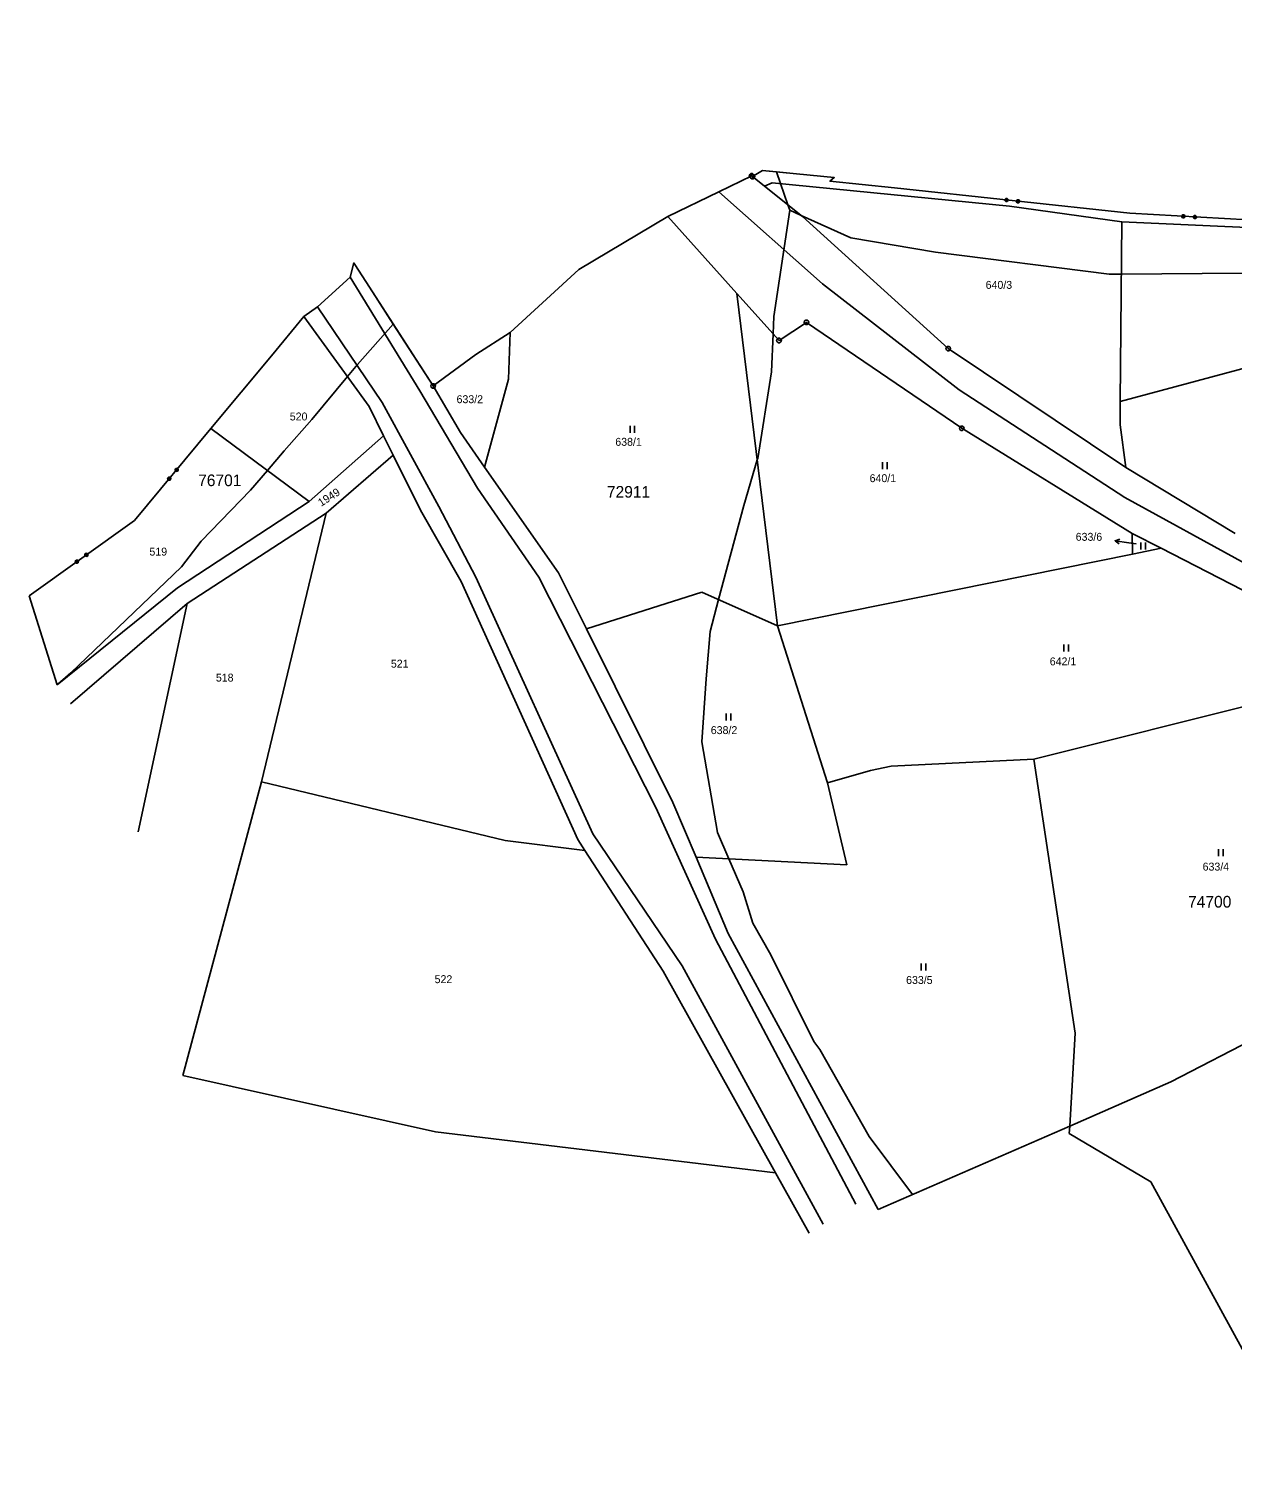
# Model space of a CAD drawing. Extents: x -789470 to -786707, y -1118640 to -1114455.
# Drawn here: x -789470 to -789211.5, y -1114767.1 to -1114454.9 of the extents above; entities that cross this region are included whole.
import ezdxf

# ---------------------------------------------------------------- set-up
doc = ezdxf.new("R2010")
doc.units = 0
for name, color, linetype in [('1', 7, 'Continuous'), ('11', 7, 'Continuous'), ('2', 7, 'Continuous'), ('3', 7, 'Continuous'), ('4', 7, 'Continuous'), ('6', 7, 'Continuous'), ('7', 7, 'Continuous'), ('8', 7, 'Continuous')]:
    doc.layers.add(name, color=color, linetype=linetype)

msp = doc.modelspace()

# ---------------------------------------------------------------- linework, layer by layer
at = {"layer": '1'}
for p, q in [((-789314.84, -1114486.39), (-789321.86, -1114489.79)), ((-789314.65, -1114486.55), (-789314.84, -1114486.39)), ((-789312.54, -1114485.23), (-789314.65, -1114486.55)), ((-789314.65, -1114486.55), (-789312.07, -1114488.61)), ((-789305.22, -1114485.95), (-789312.54, -1114485.23)), ((-789297.1, -1114486.75), (-789305.22, -1114485.95)), ((-789297.1, -1114486.75), (-789298.04, -1114487.53)), ((-789321.86, -1114489.79), (-789332.87, -1114495.13)), ((-789310.41, -1114487.87), (-789312.07, -1114488.61)), ((-789312.07, -1114488.61), (-789303.95, -1114495.11)), ((-789259.48, -1114492.92), (-789310.41, -1114487.87)), ((-789298.04, -1114487.53), (-789284.18, -1114488.99)), ((-789284.18, -1114488.99), (-789233.65, -1114494.43)), ((-789235.33, -1114496.28), (-789259.48, -1114492.92)), ((-789332.87, -1114495.13), (-789351.99, -1114506.47)), ((-789332.87, -1114495.13), (-789318.04, -1114511.65)), ((-789303.95, -1114495.11), (-789272.62, -1114523.48)), ((-789235.7, -1114534.82), (-789235.33, -1114496.28)), ((-789235.33, -1114496.28), (-789205.27, -1114497.63)), ((-789233.65, -1114494.43), (-789208.22, -1114495.86)), ((-789098.37, -1114498.11), (-789235.7, -1114534.82)), ((-789400.29, -1114505.09), (-789401.09, -1114508.13)), ((-789400.07, -1114505.43), (-789400.29, -1114505.09)), ((-789397.71, -1114509.09), (-789400.07, -1114505.43)), ((-789401.09, -1114508.13), (-789408.1, -1114514.5)), ((-789351.99, -1114506.47), (-789366.73, -1114520.04)), ((-789396.3, -1114511.28), (-789397.71, -1114509.09)), ((-789383.25, -1114531.51), (-789396.3, -1114511.28)), ((-789309.27, -1114583.03), (-789318.04, -1114511.65)), ((-789318.04, -1114511.65), (-789308.97, -1114521.75)), ((-789408.1, -1114514.5), (-789410.99, -1114516.56)), ((-789418, -1114525), (-789410.99, -1114516.56)), ((-789410.99, -1114516.56), (-789396.98, -1114535.89)), ((-789308.97, -1114521.75), (-789303.08, -1114517.85)), ((-789303.08, -1114517.85), (-789269.72, -1114540.6)), ((-789366.73, -1114520.04), (-789374.05, -1114524.74)), ((-789366.73, -1114520.04), (-789367.05, -1114530.02)), ((-789272.62, -1114523.48), (-789234.48, -1114549.02)), ((-789418, -1114525), (-789430.96, -1114540.62)), ((-789374.05, -1114524.74), (-789383.25, -1114531.51)), ((-789367.05, -1114530.02), (-789372.22, -1114548.94)), ((-789383.25, -1114531.51), (-789377.37, -1114541.51)), ((-789396.98, -1114535.89), (-789393.88, -1114542.19)), ((-789235.7, -1114534.82), (-789235.71, -1114539.82)), ((-789235.71, -1114539.82), (-789234.48, -1114549.02)), ((-789447.37, -1114560.39), (-789430.96, -1114540.62)), ((-789430.96, -1114540.62), (-789409.89, -1114556.32)), ((-789409.89, -1114556.32), (-789393.88, -1114542.19)), ((-789393.88, -1114542.19), (-789391.8, -1114546.4)), ((-789377.37, -1114541.51), (-789372.22, -1114548.94)), ((-789269.72, -1114540.6), (-789233.09, -1114563.18)), ((-789391.8, -1114546.4), (-789406.25, -1114558.84)), ((-789391.8, -1114546.4), (-789385.98, -1114558.19)), ((-789372.22, -1114548.94), (-789356.32, -1114571.64)), ((-789211.01, -1114563.21), (-789234.48, -1114549.02)), ((-789409.89, -1114556.32), (-789438.14, -1114574.88)), ((-789406.25, -1114558.84), (-789436.07, -1114578.19)), ((-789406.25, -1114558.84), (-789420.11, -1114616.54)), ((-789385.98, -1114558.19), (-789377.23, -1114573.5)), ((-789447.37, -1114560.39), (-789470.03, -1114576.58)), ((-789233.09, -1114563.18), (-789233.08, -1114567.59)), ((-789226.93, -1114566.34), (-789233.09, -1114563.18)), ((-789233.08, -1114567.59), (-789309.27, -1114583.03)), ((-789226.93, -1114566.34), (-789233.08, -1114567.59)), ((-789185.19, -1114587.78), (-789226.93, -1114566.34)), ((-789377.23, -1114573.5), (-789352.2, -1114628.9)), ((-789356.32, -1114571.64), (-789350.34, -1114583.64)), ((-789463.99, -1114595.65), (-789470.03, -1114576.58)), ((-789438.14, -1114574.88), (-789463.99, -1114595.65)), ((-789325.57, -1114575.75), (-789350.34, -1114583.64)), ((-789309.27, -1114583.03), (-789325.57, -1114575.75)), ((-789436.07, -1114578.19), (-789461.11, -1114599.74)), ((-789436.07, -1114578.19), (-789446.6, -1114627.26)), ((-789350.34, -1114583.64), (-789331.75, -1114620.93)), ((-789309.27, -1114583.03), (-789298.53, -1114616.71)), ((-789254.23, -1114611.62), (-789182.53, -1114593.72)), ((-789284.91, -1114613.12), (-789254.23, -1114611.62)), ((-789254.23, -1114611.62), (-789245.35, -1114670.48)), ((-789298.53, -1114616.71), (-789289.31, -1114614.09)), ((-789289.31, -1114614.09), (-789284.91, -1114613.12)), ((-789420.11, -1114616.54), (-789436.98, -1114679.58)), ((-789420.11, -1114616.54), (-789367.8, -1114629.1)), ((-789298.53, -1114616.71), (-789294.37, -1114634.36)), ((-789331.75, -1114620.93), (-789326.78, -1114632.68)), ((-789367.8, -1114629.1), (-789350.65, -1114631.28)), ((-789352.2, -1114628.9), (-789350.65, -1114631.28)), ((-789350.65, -1114631.28), (-789333.86, -1114657.16)), ((-789294.37, -1114634.36), (-789326.78, -1114632.68)), ((-789326.78, -1114632.68), (-789319.86, -1114649.05)), ((-789319.86, -1114649.05), (-789287.65, -1114708.37)), ((-789333.86, -1114657.16), (-789309.72, -1114700.45)), ((-789245.35, -1114670.48), (-789246.54, -1114690.43)), ((-789205.44, -1114670.9), (-789224.81, -1114680.95)), ((-789436.98, -1114679.58), (-789382.72, -1114691.68)), ((-789224.81, -1114680.95), (-789246.54, -1114690.43)), ((-789382.72, -1114691.68), (-789309.72, -1114700.45)), ((-789246.54, -1114690.43), (-789287.65, -1114708.37)), ((-789246.54, -1114690.43), (-789246.64, -1114692.06)), ((-789246.64, -1114692.06), (-789229.14, -1114702.4)), ((-789309.72, -1114700.45), (-789302.48, -1114713.42)), ((-789229.14, -1114702.4), (-789193.8, -1114767.06))]:
    msp.add_line(p, q, dxfattribs=at)
for points in [[(-789259.94, -1114491.28), (-789259.78, -1114491.49), (-789259.8, -1114491.76), (-789260.01, -1114491.92), (-789260.28, -1114491.89), (-789260.45, -1114491.69), (-789260.42, -1114491.42), (-789260.21, -1114491.25), (-789259.94, -1114491.28), (-789259.96, -1114491.32), (-789260.2, -1114491.29), (-789260.29, -1114491.36), (-789259.89, -1114491.4), (-789259.82, -1114491.49), (-789260.37, -1114491.43), (-789260.38, -1114491.51), (-789259.83, -1114491.57), (-789259.83, -1114491.65), (-789260.39, -1114491.59), (-789260.4, -1114491.67), (-789259.84, -1114491.73), (-789259.93, -1114491.8), (-789260.33, -1114491.76), (-789260.26, -1114491.85), (-789260.02, -1114491.87)], [(-789257.46, -1114491.54), (-789257.29, -1114491.75), (-789257.32, -1114492.02), (-789257.53, -1114492.19), (-789257.8, -1114492.16), (-789257.97, -1114491.95), (-789257.94, -1114491.68), (-789257.73, -1114491.52), (-789257.46, -1114491.54), (-789257.49, -1114491.58), (-789257.73, -1114491.56), (-789257.82, -1114491.63), (-789257.42, -1114491.67), (-789257.35, -1114491.76), (-789257.91, -1114491.7), (-789257.92, -1114491.78), (-789257.36, -1114491.84), (-789257.37, -1114491.92), (-789257.93, -1114491.86), (-789257.93, -1114491.94), (-789257.38, -1114492), (-789257.46, -1114492.07), (-789257.86, -1114492.02), (-789257.79, -1114492.11), (-789257.55, -1114492.14)], [(-789221.99, -1114494.77), (-789221.81, -1114494.97), (-789221.82, -1114495.24), (-789222.02, -1114495.41), (-789222.29, -1114495.4), (-789222.47, -1114495.2), (-789222.46, -1114494.93), (-789222.25, -1114494.75), (-789221.99, -1114494.77), (-789222, -1114494.8), (-789222.24, -1114494.79), (-789222.32, -1114494.87), (-789221.92, -1114494.89), (-789221.85, -1114494.97), (-789222.41, -1114494.94), (-789222.41, -1114495.02), (-789221.85, -1114495.05), (-789221.86, -1114495.13), (-789222.41, -1114495.1), (-789222.42, -1114495.18), (-789221.86, -1114495.21), (-789221.94, -1114495.29), (-789222.34, -1114495.27), (-789222.27, -1114495.35), (-789222.03, -1114495.36)], [(-789219.49, -1114494.91), (-789219.31, -1114495.11), (-789219.33, -1114495.38), (-789219.53, -1114495.55), (-789219.8, -1114495.54), (-789219.97, -1114495.34), (-789219.96, -1114495.07), (-789219.76, -1114494.89), (-789219.49, -1114494.91), (-789219.52, -1114494.94), (-789219.76, -1114494.93), (-789219.85, -1114495.01), (-789219.45, -1114495.03), (-789219.37, -1114495.11), (-789219.93, -1114495.08), (-789219.93, -1114495.16), (-789219.38, -1114495.19), (-789219.38, -1114495.27), (-789219.94, -1114495.24), (-789219.94, -1114495.32), (-789219.38, -1114495.35), (-789219.47, -1114495.43), (-789219.87, -1114495.41), (-789219.79, -1114495.49), (-789219.55, -1114495.5)], [(-789438.5, -1114549.2), (-789438.23, -1114549.18), (-789438.02, -1114549.35), (-789438, -1114549.62), (-789438.17, -1114549.82), (-789438.44, -1114549.85), (-789438.65, -1114549.68), (-789438.67, -1114549.41), (-789438.5, -1114549.2), (-789438.49, -1114549.25), (-789438.64, -1114549.43), (-789438.63, -1114549.55), (-789438.37, -1114549.24), (-789438.26, -1114549.23), (-789438.62, -1114549.66), (-789438.56, -1114549.71), (-789438.2, -1114549.28), (-789438.14, -1114549.33), (-789438.5, -1114549.76), (-789438.43, -1114549.81), (-789438.08, -1114549.38), (-789438.07, -1114549.49), (-789438.32, -1114549.8), (-789438.21, -1114549.79), (-789438.06, -1114549.61)], [(-789440.09, -1114551.12), (-789439.83, -1114551.1), (-789439.62, -1114551.27), (-789439.59, -1114551.54), (-789439.77, -1114551.75), (-789440.03, -1114551.77), (-789440.24, -1114551.6), (-789440.27, -1114551.33), (-789440.09, -1114551.12), (-789440.07, -1114551.16), (-789440.22, -1114551.34), (-789440.21, -1114551.45), (-789439.96, -1114551.15), (-789439.84, -1114551.14), (-789440.2, -1114551.57), (-789440.14, -1114551.62), (-789439.78, -1114551.19), (-789439.72, -1114551.24), (-789440.08, -1114551.67), (-789440.02, -1114551.72), (-789439.66, -1114551.29), (-789439.65, -1114551.4), (-789439.91, -1114551.71), (-789439.79, -1114551.7), (-789439.64, -1114551.51)], [(-789457.64, -1114568.12), (-789457.91, -1114568.08), (-789458.07, -1114567.86), (-789458.02, -1114567.59), (-789457.8, -1114567.44), (-789457.54, -1114567.48), (-789457.38, -1114567.7), (-789457.42, -1114567.97), (-789457.64, -1114568.12), (-789457.66, -1114568.08), (-789457.46, -1114567.95), (-789457.44, -1114567.83), (-789457.77, -1114568.07), (-789457.88, -1114568.05), (-789457.43, -1114567.72), (-789457.47, -1114567.66), (-789457.93, -1114567.98), (-789457.97, -1114567.92), (-789457.52, -1114567.59), (-789457.57, -1114567.53), (-789458.02, -1114567.85), (-789458, -1114567.74), (-789457.68, -1114567.51), (-789457.79, -1114567.49), (-789457.98, -1114567.63)], [(-789459.68, -1114569.58), (-789459.94, -1114569.53), (-789460.1, -1114569.31), (-789460.06, -1114569.05), (-789459.84, -1114568.89), (-789459.57, -1114568.94), (-789459.41, -1114569.15), (-789459.46, -1114569.42), (-789459.68, -1114569.58), (-789459.68, -1114569.53), (-789459.48, -1114569.39), (-789459.46, -1114569.28), (-789459.79, -1114569.51), (-789459.9, -1114569.49), (-789459.44, -1114569.16), (-789459.49, -1114569.1), (-789459.95, -1114569.42), (-789459.99, -1114569.36), (-789459.54, -1114569.03), (-789459.58, -1114568.97), (-789460.04, -1114569.29), (-789460.02, -1114569.18), (-789459.7, -1114568.95), (-789459.81, -1114568.93), (-789460, -1114569.07)]]:
    msp.add_lwpolyline(points, dxfattribs=at)
at = {"layer": '11'}
for points in [[(-789309.5, -1114485.53), (-789305.22, -1114485.95), (-789297.1, -1114486.75), (-789298.04, -1114487.53), (-789284.18, -1114488.99), (-789233.65, -1114494.43), (-789208.22, -1114495.86), (-789148.09, -1114487.9), (-789114.34, -1114478.64), (-789108.83, -1114473.62), (-789102.63, -1114472.12), (-789086.93, -1114468.3), (-789058.11, -1114462.67), (-789015.34, -1114455.34), (-789012.6, -1114454.87), (-789012.14, -1114455.9), (-789009.91, -1114460.91)], [(-789306.68, -1114493.77), (-789304.24, -1114494.87), (-789293.55, -1114499.73), (-789275.34, -1114502.75), (-789238.07, -1114507.53), (-789235.44, -1114507.5), (-789200.79, -1114507.22), (-789182.14, -1114505.59), (-789165.19, -1114502.68), (-789156.72, -1114502.29), (-789146.12, -1114500.63), (-789139.76, -1114497.27), (-789108.83, -1114491.87), (-789104.67, -1114490.82), (-789097.67, -1114489.05), (-789075.77, -1114483.51), (-789058.39, -1114478.49), (-789036.35, -1114473.91), (-789021.31, -1114469.97), (-789015.99, -1114468.58), (-789009.22, -1114466.81)], [(-789391.84, -1114518.2), (-789383.25, -1114531.51), (-789374.05, -1114524.74), (-789366.73, -1114520.04), (-789351.99, -1114506.47), (-789332.87, -1114495.13), (-789321.86, -1114489.79), (-789314.84, -1114486.39), (-789314.65, -1114486.55), (-789312.54, -1114485.23), (-789309.5, -1114485.53)], [(-789309.5, -1114485.53), (-789308.64, -1114488.05), (-789307.08, -1114492.61), (-789306.68, -1114493.77)], [(-789306.68, -1114493.77), (-789310.11, -1114516.6), (-789310.25, -1114520.33), (-789310.55, -1114528.44), (-789313.55, -1114547.05), (-789313.65, -1114547.38), (-789316.53, -1114557.19), (-789321.94, -1114577.37), (-789323.78, -1114584.24), (-789324.64, -1114594.39), (-789325.51, -1114607.92), (-789322.16, -1114627.39), (-789319.72, -1114633.05), (-789316.67, -1114640.1), (-789314.56, -1114646.87), (-789310.76, -1114653.65), (-789301.47, -1114672.3), (-789300.2, -1114673.99), (-789289.64, -1114692.64), (-789280.29, -1114705.16)], [(-789470.03, -1114576.58), (-789447.37, -1114560.39), (-789430.96, -1114540.62), (-789418, -1114525), (-789410.99, -1114516.56), (-789408.1, -1114514.5), (-789401.09, -1114508.13), (-789400.29, -1114505.09), (-789400.07, -1114505.43), (-789397.71, -1114509.09), (-789396.3, -1114511.28), (-789391.84, -1114518.2)], [(-789463.85, -1114595.54), (-789461.06, -1114593.1), (-789437.29, -1114570.34), (-789433.05, -1114564.85), (-789422.44, -1114553.89), (-789418.82, -1114549.66), (-789415.22, -1114545.45), (-789409.28, -1114538.7), (-789401.64, -1114529.46), (-789399.51, -1114526.89), (-789391.84, -1114518.2)]]:
    msp.add_lwpolyline(points, dxfattribs=at)
at = {"layer": '3'}
for p, q in [((-789340.97, -1114540.08), (-789340.97, -1114541.58)), ((-789339.97, -1114541.58), (-789339.97, -1114540.08)), ((-789286.75, -1114547.87), (-789286.75, -1114549.37)), ((-789285.75, -1114549.37), (-789285.75, -1114547.87)), ((-789231.25, -1114565.14), (-789231.25, -1114566.64)), ((-789230.25, -1114566.64), (-789230.25, -1114565.14)), ((-789247.8, -1114587.02), (-789247.8, -1114588.52)), ((-789246.8, -1114588.52), (-789246.8, -1114587.02)), ((-789320.31, -1114601.81), (-789320.31, -1114603.31)), ((-789319.31, -1114603.31), (-789319.31, -1114601.81)), ((-789214.56, -1114630.97), (-789214.56, -1114632.47)), ((-789213.56, -1114632.47), (-789213.56, -1114630.97)), ((-789278.45, -1114655.5), (-789278.45, -1114657)), ((-789277.45, -1114657), (-789277.45, -1114655.5))]:
    msp.add_line(p, q, dxfattribs=at)
at = {"layer": '4'}
for p, q in [((-789401.09, -1114508.13), (-789386.13, -1114532.54)), ((-789394.2, -1114535.07), (-789408.1, -1114514.5)), ((-789386.13, -1114532.54), (-789373.7, -1114553.48)), ((-789382, -1114557.37), (-789394.2, -1114535.07)), ((-789373.7, -1114553.48), (-789360.57, -1114572.59)), ((-789374.1, -1114572.59), (-789382, -1114557.37)), ((-789348.92, -1114627.7), (-789374.1, -1114572.59)), ((-789360.57, -1114572.59), (-789335.44, -1114622.02)), ((-789335.44, -1114622.02), (-789322.62, -1114650.31)), ((-789329.74, -1114656.01), (-789348.92, -1114627.7)), ((-789322.62, -1114650.31), (-789292.5, -1114707.22)), ((-789299.47, -1114711.47), (-789329.74, -1114656.01))]:
    msp.add_line(p, q, dxfattribs=at)
at = {"layer": '6'}
for p, q in [((-789299.63, -1114509.61), (-789321.86, -1114489.79)), ((-789270.25, -1114532.31), (-789299.63, -1114509.61)), ((-789234.69, -1114555.47), (-789270.25, -1114532.31)), ((-789208.89, -1114569.65), (-789234.69, -1114555.47))]:
    msp.add_line(p, q, dxfattribs=at)
at = {"layer": '7'}
for p in [(-789236.8, -1114564.74), (-789232.29, -1114565.41)]:
    msp.add_line(p, (-789233.83, -1114565.18), dxfattribs=at)
msp.add_lwpolyline([(-789235.88, -1114565.38), (-789236.8, -1114564.74), (-789235.74, -1114564.39)], dxfattribs=at)
at = {"layer": '8'}
for p, q in [((-789314.96, -1114486.39), (-789314.72, -1114486.39)), ((-789314.77, -1114486.55), (-789314.53, -1114486.55)), ((-789303.2, -1114517.85), (-789302.96, -1114517.85)), ((-789309.09, -1114521.75), (-789308.85, -1114521.75)), ((-789272.74, -1114523.48), (-789272.5, -1114523.48)), ((-789383.37, -1114531.51), (-789383.13, -1114531.51)), ((-789269.84, -1114540.6), (-789269.6, -1114540.6))]:
    msp.add_line(p, q, dxfattribs=at)
for points in [[(-789314.69, -1114485.91), (-789314.44, -1114486.09), (-789314.34, -1114486.38), (-789314.44, -1114486.67), (-789314.69, -1114486.85), (-789315, -1114486.85), (-789315.25, -1114486.67), (-789315.35, -1114486.38), (-789315.25, -1114486.09), (-789315, -1114485.91)], [(-789314.5, -1114486.07), (-789314.25, -1114486.25), (-789314.15, -1114486.54), (-789314.25, -1114486.83), (-789314.5, -1114487.01), (-789314.81, -1114487.01), (-789315.06, -1114486.83), (-789315.16, -1114486.54), (-789315.06, -1114486.25), (-789314.81, -1114486.07)], [(-789302.93, -1114517.37), (-789302.68, -1114517.55), (-789302.58, -1114517.84), (-789302.68, -1114518.13), (-789302.93, -1114518.31), (-789303.24, -1114518.31), (-789303.49, -1114518.13), (-789303.59, -1114517.84), (-789303.49, -1114517.55), (-789303.24, -1114517.37)], [(-789308.82, -1114521.27), (-789308.57, -1114521.45), (-789308.47, -1114521.74), (-789308.57, -1114522.03), (-789308.82, -1114522.21), (-789309.13, -1114522.21), (-789309.38, -1114522.03), (-789309.48, -1114521.74), (-789309.38, -1114521.45), (-789309.13, -1114521.27)], [(-789272.47, -1114523), (-789272.22, -1114523.18), (-789272.12, -1114523.47), (-789272.22, -1114523.76), (-789272.47, -1114523.94), (-789272.78, -1114523.94), (-789273.03, -1114523.76), (-789273.13, -1114523.47), (-789273.03, -1114523.18), (-789272.78, -1114523)], [(-789383.1, -1114531.03), (-789382.85, -1114531.21), (-789382.75, -1114531.5), (-789382.85, -1114531.79), (-789383.1, -1114531.97), (-789383.41, -1114531.97), (-789383.66, -1114531.79), (-789383.76, -1114531.5), (-789383.66, -1114531.21), (-789383.41, -1114531.03)], [(-789269.57, -1114540.12), (-789269.32, -1114540.3), (-789269.22, -1114540.59), (-789269.32, -1114540.88), (-789269.57, -1114541.06), (-789269.88, -1114541.06), (-789270.13, -1114540.88), (-789270.23, -1114540.59), (-789270.13, -1114540.3), (-789269.88, -1114540.12)]]:
    msp.add_lwpolyline(points, close=True, dxfattribs=at)

# ---------------------------------------------------------------- texts
at = {"layer": '11'}
for s, p in [('76701', (-789433.72, -1114553.02)), ('72911', (-789345.93, -1114555.49)), ('74700', (-789221.12, -1114643.51))]:
    msp.add_text(s, height=2.5, dxfattribs=at).set_placement(p)
at = {"layer": '2'}
for s, height, p in [('640/3', 1.7, (-789264.59, -1114510.65)), ('633/2', 1.7, (-789378.22, -1114535.2)), ('520', 1.7, (-789414.04, -1114538.91)), ('638/1', 1.7, (-789344.13, -1114544.35)), ('640/1', 1.7, (-789289.51, -1114552.16)), ('519', 1.7, (-789444.18, -1114567.93)), ('633/6', 0.1, (-789232.5, -1114565.41)), ('642/1', 1.7, (-789250.82, -1114591.5)), ('521', 1.7, (-789392.33, -1114591.99)), ('518', 1.7, (-789429.91, -1114594.98)), ('638/2', 1.7, (-789323.62, -1114606.26)), ('633/4', 1.7, (-789217.99, -1114635.57)), ('522', 1.7, (-789382.93, -1114659.74)), ('633/5', 1.7, (-789281.67, -1114659.91))]:
    msp.add_text(s, height=height, dxfattribs=at).set_placement(p)
msp.add_text('1949', height=1.7, rotation=32.7732, dxfattribs=at).set_placement((-789407.3, -1114557.47))
at = {"layer": '7'}
msp.add_text('633/6', height=1.7, dxfattribs=at).set_placement((-789245.25, -1114564.75))

doc.saveas('drawing.dxf')
